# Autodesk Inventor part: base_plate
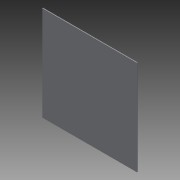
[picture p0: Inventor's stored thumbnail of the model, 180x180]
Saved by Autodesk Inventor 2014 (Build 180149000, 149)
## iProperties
Created: 2008-04
Part Number: base_plate
Document SubType Name: Modeling
Designer: Jayson Martinez
Density: 1 g/cm^3
Material: Generic
Appearance: Default
Width: 24.000 in
PlateThickness: 0.200 in
Height: 12.000 in
MemberThickness: 0.125 in
MemberWidth: 2.000 in
HorizontalLength: 20.000 in
CornerLength: 12.000 in
SideLength: 8.000 in
Author: Jayson Martinez
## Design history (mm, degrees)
sketch "Sketch1"
  geometry: L1 (0, 0)-(609.6, 0); L2 (609.6, 0)-(609.6, 609.6); L3 (609.6, 609.6)-(0, 609.6); L4 (0, 609.6)-(0, 0)
  constraints: 8 end point, 2 parallel, 1 horizontal, 1 perpendicular
  dimensions: "d3" = 609.6 distance of L1.start L1.end (= Width); "d4" = 609.6 distance of L3.end L1.start (= Width)
extrude "Extrusion1" new body sketch "Sketch1" distance "d0" = 5.08 (= PlateThickness); taper "d1" = 0 deg
sketch "Sketch2"
  geometry: L1 (304.8, 609.6)-(304.8, 0); L2 (609.6, 0)-(0, 0) reference; L3 (0, 609.6)-(609.6, 609.6) reference; C1 r 299.999 at (304.8, 304.8); 1 further point
  constraints: 3 midpoint, 2 end point, 1 centre point, 1 coincident
  dimensions: "d2" = 599.9988 diameter of C1
split "Split1" sketch "Sketch2"
workplane "Work Plane1"
body "Solid1"
other parameters: "Width" = 609.6 [user parameter; used in 4 equation terms], "PlateThickness" = 5.08 [user parameter; used in 1 equation term], "d6" = 304.8 (= 0.5 x Width), "Height" = 304.8 [user parameter; used in 2 equation terms], "MemberThickness" = 3.175 [user parameter], "MemberWidth" = 50.8 [user parameter; used in 2 equation terms], "HorizontalLength" = 508 (= Width - 2 x MemberWidth) [user parameter], "CornerLength" = 304.8 (= Height) [user parameter], "SideLength" = 203.2 (= Height - 2 x MemberWidth) [user parameter]
